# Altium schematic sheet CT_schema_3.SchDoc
size 357 x 184 mm
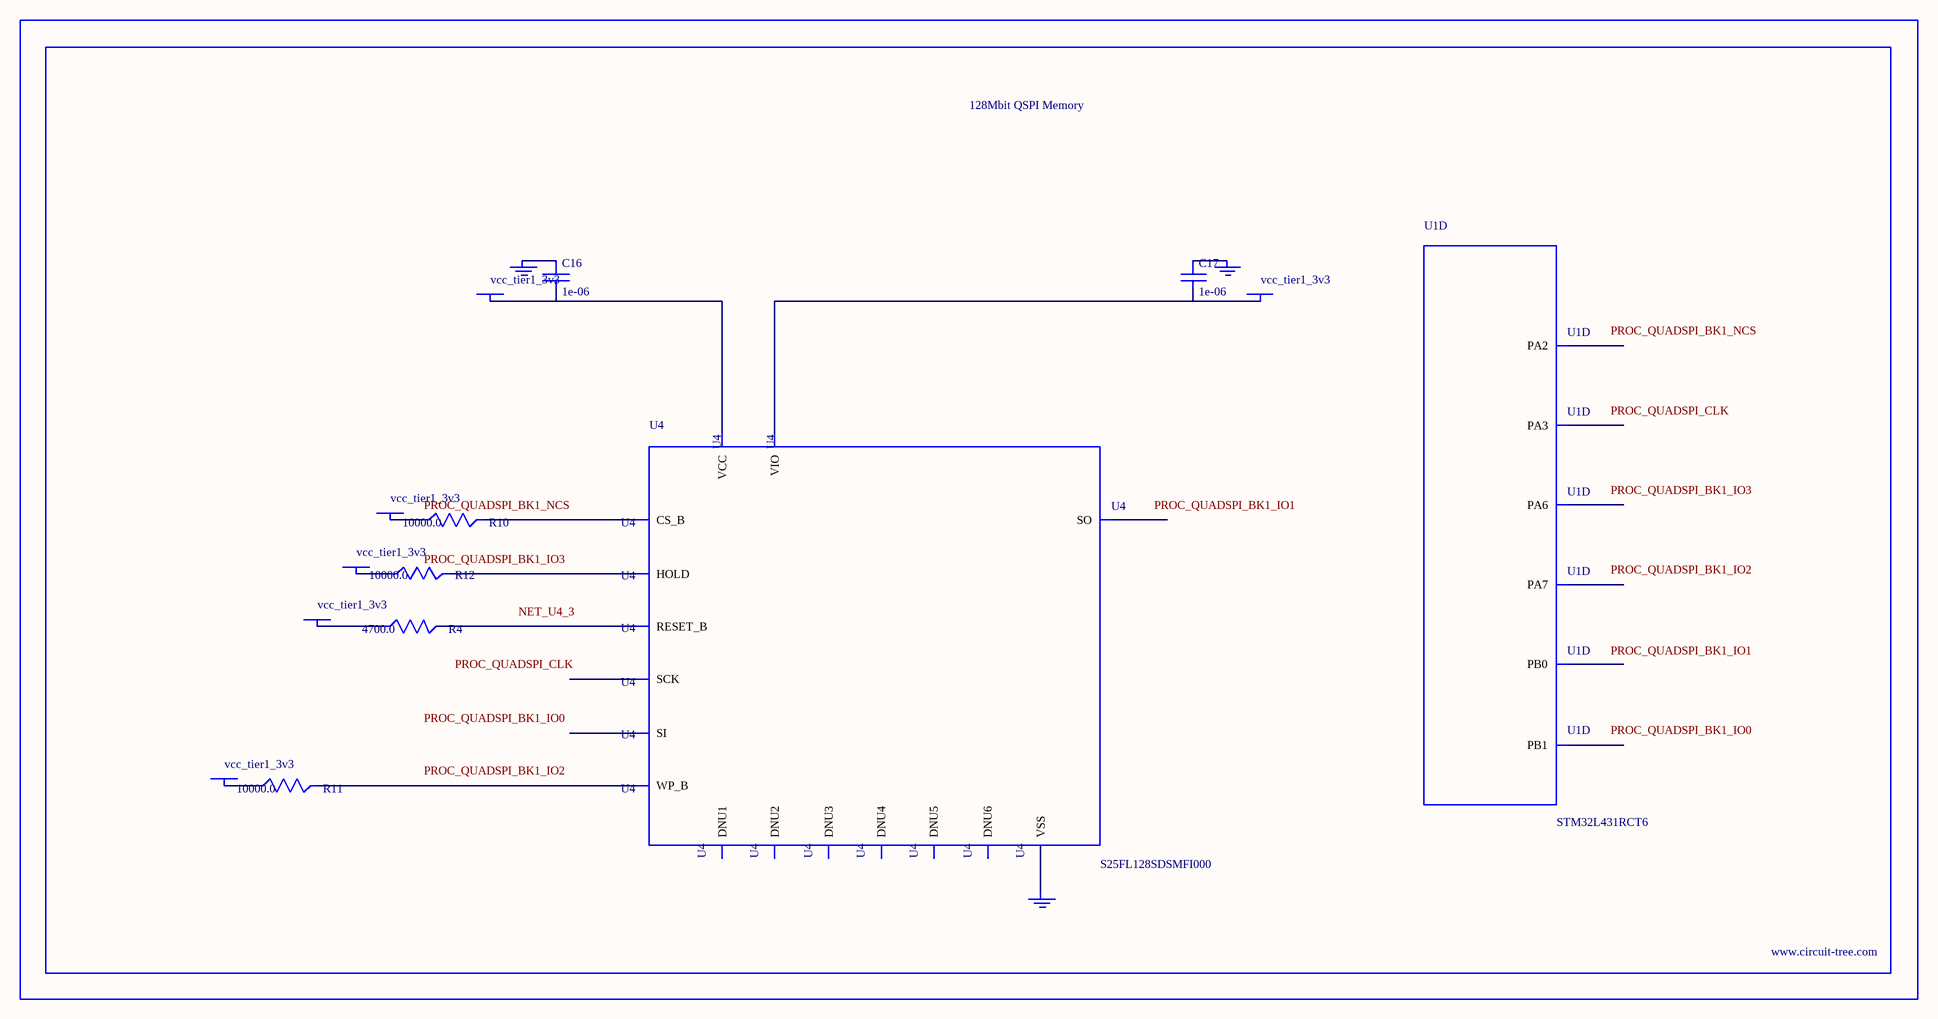
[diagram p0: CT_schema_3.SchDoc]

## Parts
BORDER2  (no value)
C16  1e-06  [C0603]
C17  1e-06  [C0603]
GND_INSTANCE_2_0  (no value)
GND_INSTANCE_2_1  (no value)
GND_INSTANCE_2_2  (no value)
POWER_INSTANCE_2_0  vcc_tier1_3v3
POWER_INSTANCE_2_1  vcc_tier1_3v3
POWER_INSTANCE_2_2  vcc_tier1_3v3
POWER_INSTANCE_2_3  vcc_tier1_3v3
POWER_INSTANCE_2_4  vcc_tier1_3v3
POWER_INSTANCE_2_5  vcc_tier1_3v3
R4  4700.0  [R0603]
R10  10000.0  [R0603]
R11  10000.0  [R0603]
R12  10000.0  [R0603]
U1  STM32L431RCT6  [LQFP64]  (part D of 6)
U4  S25FL128SDSMFI000  [S25FL128SDSMFI000]

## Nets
NetC16_1: C16.1 GND_INSTANCE_2_0.0(GND)
NetC16_2: C16.2 POWER_INSTANCE_2_1.0(PWR) U4.2(VCC)
NetC17_1: C17.1 GND_INSTANCE_2_1.0(GND)
NetC17_2: C17.2 POWER_INSTANCE_2_4.0(PWR) U4.14(VIO)
NetGND_INSTANCE_2_2_0: GND_INSTANCE_2_2.0(GND) U4.10(VSS)
NetPOWER_INSTANCE_2_0_0: POWER_INSTANCE_2_0.0(PWR) R12.1
NetPOWER_INSTANCE_2_2_0: POWER_INSTANCE_2_2.0(PWR) R10.1
NetPOWER_INSTANCE_2_3_0: POWER_INSTANCE_2_3.0(PWR) R11.1
NetPOWER_INSTANCE_2_5_0: POWER_INSTANCE_2_5.0(PWR) R4.1
NetR4_2: R4.2 U4.3(RESET_B)
NetR10_2: R10.2 U4.7(CS_B)
NetR11_2: R11.2 U4.9(WP_B)
NetR12_2: R12.2 U4.1(HOLD)

Not connected (* = marked no-connect by the designer): U1 16(PA2) 17(PA3) 22(PA6) 23(PA7) 26(PB0) 27(PB1); U4 4(DNU1) 5(DNU2) 6(DNU6) 8(SO) 11(DNU3) 12(DNU4) 13(DNU5) 15(SI) 16(SCK)

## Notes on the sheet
- Labels drawn without touching a wire or pin: NET_U4_3, PROC_QUADSPI_BK1_IO0, PROC_QUADSPI_BK1_IO1, PROC_QUADSPI_BK1_IO2, PROC_QUADSPI_BK1_IO3, PROC_QUADSPI_BK1_NCS, PROC_QUADSPI_CLK

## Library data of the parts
BORDER2 = BORDER_PAGE2
C16 C17 = C0603C105K3RACTU
GND_INSTANCE_2_0-GND_INSTANCE_2_2 = GND
POWER_INSTANCE_2_0-POWER_INSTANCE_2_5 = PWR
R4 = RC0603JR-074K7L
R10-R12 = RC0603JR-0710KL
